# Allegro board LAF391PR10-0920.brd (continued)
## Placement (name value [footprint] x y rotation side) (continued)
JLED1  CVILU_CF5006FD0R0-05-NH  [CVILU_CF5006FD0R0-05-NH_6P]  271.3 9.4 0 top
JLOM1  SANTA_130456-821  [SANTA_130456-821_13P-T]  286.87 80.53 270 bottom
JNGFF1  CONCR_213AAAA42FA  [CONCR_213AAAA42FA_75P]  210.18 38.5 270 bottom
JNGFF2  CONCR_213BAAA42FA  [CONCR_213BAAA42FA_75P]  258.75 28.93 0 bottom
JNGFF3  LCN_DAN05-67356-0103  [LCN_DAN05-67356-0103_75P]  281.1 10.02 180 bottom
JRTC1  ACES_50271-0020N-001  [ACES_50271-0020N-001_2P]  48.15 75.49 90 bottom
JSATA1  ACES_59003-02006-002  [ACES_59003-02006-002_20P]  245.9 7.33 0 bottom
JSD1  T-SOL_158-1000902614  [T-SOL_158-1000902614_23P-T]  85.18 97.85 180 top
JSIM1  T-SOL_5-991503004000-6  [T-SOL_5-991503004000-6_8P-T]  112.1 97.08 0 bottom
JSPI1  ACES_50506-02041-P01  [ACES_50506-02041-P01_20P]  167.6 67.9 325 bottom
JSPK1  ACES_50271-0060N-001  [ACES_50271-0060N-001_6P-T]  257.05 22 270 bottom
JTAG1  @SHORT PADS~D  [SHORTPADS]  274.47 52.78 0 top
JUSB1  ACON_TCRA2-9U1U93  [ACON_TCRA2-9U1U93_9P-T]  285.2 19.95 270 bottom
JUSB2  ACON_TCRA2-9U1U93  [ACON_TCRA2-9U1U93_9P-T]  15.9 29.2 90 bottom
JUSBC1  JAE_DX07BD24JJ2  [JAE_DX07BD24JJ2_24P-T]  7.6 68.86 90 bottom
JUSH1  CVILU_CF5026FD0RK-05-NH  [CVILU_CF5026FD0RK-05-NH_26P-T]  251.1 9.93 0 top
JXDP1  SAMTE_BSH-030-01-L-D-A  [SAMTE_BSH-030-01-L-D-A_60P]  103.14 98.04 180 bottom
LA5  BLM15PX600SN1D_2P  [MURAT_BLM15PX600SN1D_2P]  268.96 24.94 0 top
LA6  BLM15PX330SN1D_2P  [MURAT_BLM15PX330SN1D_2P]  265.75 26.97 0 top
LA7  BLM15PX330SN1D_2P  [MURAT_BLM15PX330SN1D_2P]  263.85 26.97 0 top
LA8  BLM15PX330SN1D_2P  [MURAT_BLM15PX330SN1D_2P]  260.99 26.97 180 top
LA9  BLM15PX330SN1D_2P  [MURAT_BLM15PX330SN1D_2P]  262.95 26.97 180 top
LA10  BLM15PX330SN1D_2P  [MURAT_BLM15PX330SN1D_2P]  273.64 16.91 270 top
LA11  BLM15PX330SN1D_2P  [MURAT_BLM15PX330SN1D_2P]  273.59 18.34 90 top
LA12  BLM15PX600SN1D_2P  [MURAT_BLM15PX600SN1D_2P]  261.38 14.4 0 top
LA13  HCB2012KF-121T50_2P  [TAI-T_HCB2012KF-121T50_2P]  256.95 28.41 90 top
LA14  BLM15PX600SN1D_2P  [MURAT_BLM15PX600SN1D_2P]  254.18 25.15 270 top
LA15  BLM15PX330SN1D_2P  [MURAT_BLM15PX330SN1D_2P]  278.72 7.88 90 top
LA16  BLM15PX330SN1D_2P  [MURAT_BLM15PX330SN1D_2P]  278.72 5.86 270 top
LC1  BLM15GA750SN1D_2P  [MURAT_BLM15GA750SN1D_2P]  127.95 60.12 0 top
LC2  BLM15GA750SN1D_2P  [MURAT_BLM15GA750SN1D_2P]  153.9 68.36 180 bottom
LED3  LTW-C193DC-C_WHITE  [LED_LTW-C193DC-C_2P]  294.5 94.9 0 top
LGA1  -  [LNG2DMTR_LGA12_2X2]  244.76 11.55 270 bottom
LI3  EXC24CQ900U_4P  [PANAS_EXC24CQ900U_4P]  25.83 20.93 270 top
LI7  EXC24CQ900U_4P  [PANAS_EXC24CQ900U_4P]  276.83 26.33 0 top
LI8  MCM1012B900F06BP_4P  [INPAQ_MCM1012B900F06BP_4P]  252.5 28.76 0 top
LI9  MCM1012B900F06BP_4P  [INPAQ_MCM1012B900F06BP_4P]  205.68 37.64 0 bottom
LI16  HCM1012GH900BP_4P  [INPAQ_HCM1012GH900BP_4P]  253.45 31.51 0 bottom
LI17  HCM1012GH900BP_4P  [INPAQ_HCM1012GH900BP_4P]  253.45 33.32 0 bottom
LL1  4.7UH_BRC2012T4R7MD_20%  [TAIYO_BRC2012T4R7MD_2P]  263.1 68.65 0 top
LL2  BLM15PX181SN1D_2P  [MURAT_BLM15PX181SN1D_2P]  257.75 67.05 270 top
LT11  BLM15PX600SN1D_2P  [MURAT_BLM15PX600SN1D_2P]  23.47 81.35 270 top
LV1  BLM15PX221SN1D_2P  [MURAT_BLM15PX221SN1D_2P]  67.99 95.42 0 top
LV3  HCM1012GH900BP_4P  [TAIYO_MCF12102G900-T_4P-NPM]  18.33 43.57 180 bottom
LV6  HCM1012GH900BP_4P  [TAIYO_MCF12102G900-T_4P-NPM]  18.33 47.19 180 bottom
LV9  HCM1012GH900BP_4P  [TAIYO_MCF12102G900-T_4P-NPM]  18.33 45.41 180 bottom
LV12  HCM1012GH900BP_4P  [TAIYO_MCF12102G900-T_4P-NPM]  18.33 48.96 180 bottom
LV14  BLM15PX600SN1D_2P  [MURAT_BLM15PX600SN1D_2P]  280.09 43.74 90 top
LV16  BLM15BB470SN1D_2P  [MURAT_BLM15BB470SN1D_2P]  284.03 61.51 270 top
LV17  BLM15BB470SN1D_2P  [MURAT_BLM15BB470SN1D_2P]  284.03 59.48 270 top
LV18  BLM15BB470SN1D_2P  [MURAT_BLM15BB470SN1D_2P]  284.03 56.54 90 top
LV27  EXC24CQ900U_4P  [PANAS_EXC24CQ900U_4P]  71.64 107.03 90 top
LV30  BLM15PX600SN1D_2P  [MURAT_BLM15PX600SN1D_2P]  284.03 53.64 270 top
LZ1  EXC24CQ900U_4P  [PANAS_EXC24CQ900U_4P]  72.19 101.01 270 top
NOREF  -  []  184.95 77.1 0 top
NOREF#2  -  []  91.15 74.3 0 top
NOREF#3  -  []  124.55 20.7 0 top
NOREF#4  -  []  65.55 78.35 0 top
NOREF#5  -  []  247.75 59.6 0 top
NOREF#6  -  []  149.55 49.8 0 top
NOREF#7  -  []  21.05 15.3 0 top
NOREF#8  -  []  268 74.45 0 top
NOREF#9  -  []  8.85 36.75 0 top
NOREF#10  -  []  25.35 10.82 0 top
NOREF#11  -  []  7.55 12.7 0 top
NOREF#12  -  []  288.05 36.75 0 top
NOREF#13  -  []  91.15 49.8 0 top
NOREF#14  -  []  298.51 26.78 0 top
NOREF#15  -  []  124.55 13.2 0 top
NOREF#16  -  []  6.15 62.43 0 top
NOREF#17  -  []  15.55 38.05 0 top
NOREF#18  -  []  68.06 33.65 0 top
NOREF#19  -  []  151.05 105.15 0 top
NOREF#20  -  []  38.55 100.6 0 top
NOREF#21  -  []  117.34 -26.12 0 top
NOREF#22  -  []  85.37 39.58 0 top
NOREF#23  -  []  243.7 29.25 0 top
NOREF#24  -  []  98.99 -5.54 0 top
NOREF#25  -  []  149.55 74.3 0 top
NOREF#26  -  []  102.02 31.33 90 top
NOREF#27  -  []  6.15 80.53 0 top
NOREF#28  -  []  108.67 25.88 0 top
NOREF#29  -  []  283.55 93.6 0 top
NOREF#30  -  []  280.05 15.3 0 top
NOREF#31  -  []  22.25 161.39 0 top
NOREF#32  -  []  142.57 28.51 180 bottom
NOREF#33  -  []  68.15 26.49 180 bottom
NOREF#34  -  []  161.08 0.92 180 bottom
NOREF#35  -  []  110.93 37.72 180 bottom
PBATT1  DEREN_40-42251-01001RHF  [DEREN_40-42251-01001RHF_10P-T]  41.3 24.06 180 bottom
PC1  2200P_0402_50V7K  [C_0402]  45.84 23.81 270 top
PC2  2200P_0402_50V7K  [C_0402]  45.51 80.75 270 top
PC3  1U_0603_25V6K  [C_0603]  47.96 83.07 0 top
PC4  0.022U_0603_50V7K  [C_0603]  52.92 84.78 90 bottom
PC5  1000P_0603_50V7K  [C_0603]  49.61 94.9 0 top
PC6  0.022U_0603_50V7K  [C_0603]  49.48 92.65 0 bottom
PC7  0.1U_0603_25V7K  [C_0603]  52.72 94.77 90 top
PC8  10U_0805_25V6K  [C_0805]  56.96 91.89 90 top
PC9  0.1U_0402_10V7K  [C_0402]  53.48 90.6 90 bottom
PC10  2.2U_0402_10V6M  [C_0402]  57.18 78 270 bottom
PC11  1000P_0603_50V7K  [C_0603]  53.54 79.18 180 bottom
PC100  100P_0402_50V8J  [C_0402]  147.63 110.49 270 top
PC102  0.1U_0603_25V7K  [C_0603]  140.39 110.97 270 bottom
PC103  100P_0402_50V8J  [C_0402]  147.63 110.49 270 bottom
PC104  10U_0805_25V6K  [C_0805]  146.23 110.5 270 bottom
PC105  10U_0805_25V6K  [C_0805]  146.23 110.5 270 top
PC106  22UF_0805_6.3V6M  [C_0805]  130.07 105.08 180 top
PC107  22UF_0805_6.3V6M  [C_0805]  130.07 108.63 180 top
PC108  22UF_0805_6.3V6M  [C_0805]  130.07 106.85 180 top
PC109  22UF_0805_6.3V6M  [C_0805]  130.07 105.08 180 bottom
PC110  22UF_0805_6.3V6M  [C_0805]  130.07 106.85 180 bottom
PC111  4.7U_0603_6.3V6K  [C_0603]  140.26 102.85 270 bottom
PC112  680P_0603_50V7K  [C_0603]  139.56 105.96 0 top
PC113  1000P_0402_50V7K  [C_0402]  142.3 102.87 270 bottom
PC114  0.1U_0603_25V7K  [C_0603]  46.17 46.44 180 bottom
PC115  100P_0402_50V8J  [C_0402]  43.74 39.92 180 top
PC116  100P_0402_50V8J  [C_0402]  43.74 39.92 180 bottom
PC117  10U_0805_25V6K  [C_0805]  44.12 41.32 180 bottom
PC118  10U_0805_25V6K  [C_0805]  44.12 41.32 180 top
PC119  4.7U_0603_6.3V6K  [C_0603]  40.32 47.65 180 bottom
PC120  22UF_0805_6.3V6M  [C_0805]  38.94 53.22 180 bottom
PC121  22UF_0805_6.3V6M  [C_0805]  38.94 51.51 180 top
PC122  22UF_0805_6.3V6M  [C_0805]  38.92 49.79 180 top
PC123  22UF_0805_6.3V6M  [C_0805]  38.94 51.51 180 bottom
PC124  22UF_0805_6.3V6M  [C_0805]  38.94 53.22 180 top
PC125  680P_0603_50V7K  [C_0603]  42.85 49.71 270 top
PC126  4.7U_0603_6.3V6K  [C_0603]  40.1 45.74 90 top
PC127  1000P_0402_50V7K  [C_0402]  38.79 44.62 270 bottom
PC128  4.7U_0603_6.3V6K~D  [C_0603]  39.41 42.57 180 top
PC129  22UF_0805_6.3V6M  [C_0805]  130.07 108.63 180 bottom
PC130  22UF_0805_6.3V6M  [C_0805]  38.92 49.79 180 bottom
PC131  100P_0402_50V8J  [C_0402]  43.86 44.65 180 top
PC132  100P_0402_50V8J  [C_0402]  38.53 54.52 180 bottom
PC133  1000P_0402_50V7K  [C_0402]  164.43 108.6 180 top
PC134  1000P_0402_50V7K  [C_0402]  162.87 110.37 270 top
PC135  1U_0402_25V6K  [C_0402]  162.01 110.35 270 top
PC136  1U_0402_25V6K  [C_0402]  161.14 110.34 270 top
PC137  1000P_0402_50V7K  [C_0402]  49.38 43.71 90 top
PC138  1000P_0402_50V7K  [C_0402]  48.51 43.69 90 top
PC139  1U_0402_25V6K  [C_0402]  49.77 40.34 270 top
PC140  1U_0402_25V6K  [C_0402]  48.89 40.33 270 top
PC151  100P_0402_50V8J  [C_0402]  166.81 108.84 270 top
PC152  100P_0402_50V8J  [C_0402]  47.55 44.04 90 top
PC153  100P_0402_50V8J  [C_0402]  129.42 110.03 180 bottom
PC200  10U_0603_25V6M  [C_0603]  59.43 60.37 270 bottom
PC201  10U_0603_25V6M  [C_0603]  59.43 60.37 270 top
PC202  0.1U_0402_25V6  [C_0402]  59.64 61.51 90 top
PC203  2200P_0402_50V7K  [C_0402]  58.73 61.51 90 top
PC204  680P_0603_50V7K  [C_0603]  48.95 61.77 270 bottom
PC205  0.1U_0603_16V7K  [C_0603]  52.35 61.51 270 bottom
PC206  1U_0402_6.3V6K  [C_0402]  55.56 62.89 90 top
PC207  2.2U_0402_6.3V6M  [C_0402]  56.44 62.9 90 top
PC208  330P_0402_50V7K  [C_0402]  55.66 63.88 270 bottom
PC209  22U_0603_6.3V6M  [C_0603]  54.79 55.93 270 bottom
PC210  22U_0603_6.3V6M  [C_0603]  54.77 52.18 90 top
PC211  22U_0603_6.3V6M  [C_0603]  53.62 49.77 270 top
PC212  22U_0603_6.3V6M  [C_0603]  55.96 52.18 90 top
PC213  22U_0603_6.3V6M  [C_0603]  54.77 52.18 90 bottom
PC214  10U_0603_6.3V6M  [C_0603]  55.96 52.18 90 bottom
PC216  2200P_0402_50V7K  [C_0402]  57.13 52.12 0 top
PC217  100P_0402_50V8J  [C_0402]  57.1 50.06 0 top
PC218  1U_0402_10V6K  [C_0402]  58.22 56.31 270 bottom
PC219  22U_0603_6.3V6M  [C_0603]  55.88 55.9 0 bottom
PC221  0.1U_0402_10V7K  [C_0402]  59.21 57.6 0 top
PC222  0.1U_0402_10V7K  [C_0402]  58.6 55.33 180 top
PC223  10U_0603_6.3V6M  [C_0603]  53.62 49.77 270 bottom
PC231  100P_0402_50V8J  [C_0402]  57.84 61.51 90 top
PC301  100P_0402_50V8J  [C_0402]  159.38 109.43 0 bottom
PC302  680P_0603_50V7K  [C_0603]  158.68 103.11 0 top
PC303  100P_0402_50V8J  [C_0402]  159.38 109.43 0 top
PC304  0.1U_0603_25V7K  [C_0603]  157.8 103.31 180 bottom
PC305  10U_0603_25V6M  [C_0603]  159.44 108.37 0 bottom
PC306  10U_0603_25V6M  [C_0603]  159.44 108.37 0 top
PC307  330P_0402_50V7K  [C_0402]  165.96 104.97 90 bottom
PC308  22U_0603_6.3V6M  [C_0603]  164.94 100.45 0 bottom
PC309  22U_0603_6.3V6M  [C_0603]  164.94 99.18 0 bottom
PC310  22U_0603_6.3V6M  [C_0603]  164.94 100.45 0 top
PC311  22U_0603_6.3V6M  [C_0603]  164.94 99.18 0 top
PC312  4.7U_0603_6.3V6K  [C_0603]  163.91 103.74 0 bottom
PC313  4.7U_0603_6.3V6K  [C_0603]  163.91 102.54 0 bottom
PC401  470P_0402_50V7K  [C_0402]  169.96 48.71 180 bottom
PC402  0.1U_0402_25V6  [C_0402]  177.35 48.74 90 top
PC403  10U_0603_10V6M  [C_0603]  179.32 49.77 270 bottom
PC404  10U_0603_10V6M  [C_0603]  179.32 49.77 270 top
PC406  22U_0603_6.3V6M  [C_0603]  170.44 53.92 0 bottom
PC407  22U_0603_6.3V6M  [C_0603]  170.44 52.71 0 bottom
PC408  0.1U_0402_25V6  [C_0402]  180.52 49.15 270 top
PC409  100P_0402_50V8J  [C_0402]  178.24 49.27 270 bottom
PC410  470P_0402_50V7K  [C_0402]  175.08 54.69 0 top
PC411  0.1U_0402_25V6  [C_0402]  172.85 97.35 90 top
PC412  10U_0603_10V6M  [C_0603]  175.97 99.24 270 bottom
PC413  10U_0603_10V6M  [C_0603]  175.97 99.24 270 top
PC415  22U_0603_6.3V6M  [C_0603]  169.28 95.68 0 top
PC417  0.1U_0402_25V6  [C_0402]  177.01 98.71 270 top
PC418  100P_0402_50V8J  [C_0402]  177.01 98.7 270 bottom
PC419  470P_0402_50V7K  [C_0402]  169.64 99.77 90 top
PC420  470P_0402_50V7K  [C_0402]  171.96 102.62 180 top
PC424  22U_0603_6.3V6M  [C_0603]  169.28 95.68 0 bottom
PC425  10U_0603_6.3V6M  [C_0603]  170.44 53.92 0 top
PC426  10U_0603_6.3V6M  [C_0603]  170.44 52.7 0 top
PC427  10U_0603_6.3V6M  [C_0603]  169.28 94.41 0 top
PC428  10U_0603_6.3V6M  [C_0603]  169.28 94.41 0 bottom
PC501  22U_0603_6.3V6M  [C_0603]  168.63 106.02 90 bottom
PC503  68P_0402_50V8J  [C_0402]  175.66 104.97 0 bottom
PC504  22U_0603_6.3V6M  [C_0603]  168.63 106 90 top
PC505  0.1U_0402_16V7K  [C_0402]  172.43 107.11 270 top
PC506  680P_0402_50V7K  [C_0402]  172.17 108.37 0 top
PC513  .1U_0402_16V7K  [C_0402]  220.59 11.11 270 top
PC514  4.7U_0603_6.3V6K  [C_0603]  221.37 14.35 270 top
PC515  0.01UF_0402_25V7K  [C_0402]  215.23 14.57 270 top
PC516  22U_0603_6.3V6M  [C_0603]  216.34 15.99 0 top
PC530  10U_0603_6.3V6M  [C_0603]  175.11 109.6 0 top
PC531  10U_0603_6.3V6M  [C_0603]  175.11 109.6 0 bottom
PC601  680P_0402_50V7K  [C_0402]  67.73 73.33 0 bottom
PC602  0.1U_0402_25V6  [C_0402]  59.09 65.49 90 top
PC603  1U_0603_10V6K  [C_0603]  63.01 68.28 180 top
PC604  0.22U_0603_25V7K  [C_0603]  63.02 69.48 180 top
PC605  47P_0402_50V8J~D  [C_0402]  60.87 63.75 90 top
PC606  100U_D_20VM_R55M  [C_D]  66.87 59.19 0 bottom
PC607  100U_D_20VM_R55M  [C_D]  62.4 56.49 90 bottom
PC608  10U 25V M X5R 0603 ZRB  [C_0603]  89.78 88.77 0 top
PC611  0.22U_0603_16V7K  [C_0603]  85.46 89.07 0 bottom
PC612  10U 25V M X5R 0603 ZRB  [C_0603]  89.79 88.76 0 bottom
PC613  330P_0402_50V7K  [C_0402]  66.21 65.35 270 bottom
PC614  2200P_0402_50V7K  [C_0402]  71.1 61.98 180 bottom
PC616  33P_0402_50V8J  [C_0402]  67.71 65.37 270 bottom
PC617  1200P_0402_50V7K  [C_0402]  69.13 60.44 270 top
PC618  330P_0402_50V7K  [C_0402]  70.02 59.53 90 top
PC619  0.01UF_0402_25V7K  [C_0402]  69.01 65.38 270 bottom
PC620  0.082U_0402_16V7K  [C_0402]  68.49 61.39 90 top
PC621  680P_0402_50V7K  [C_0402]  68.64 58.59 180 top
PC622  680P_0603_50V7K  [C_0603]  92.19 83.23 180 top
PC624  0.033U_0402_16V7K  [C_0402]  73.75 63.13 270 bottom
PC625  330P_0402_50V7K  [C_0402]  70.53 65.5 0 bottom
PC626  0.047U_0402_25V7K  [C_0402]  72.88 63.14 270 bottom
PC627  2200P_0402_50V7K  [C_0402]  71.54 62.27 180 top
PC628  33P 50V J NPO 0402  [C_0402]  68.71 70.08 270 bottom
PC629  2200P_0402_50V7K  [C_0402]  75.81 65.1 180 top
PC630  2200P_0402_50V7K  [C_0402]  72.16 71.1 0 top
PC631  4700P_0402_25V7K  [C_0402]  69.13 73.34 0 top
PC632  1000P_0402_50V7K  [C_0402]  64.74 71.57 90 top
PC633  4700P 50V K X7R 0402  [C_0402]  66.5 71.56 90 top
PC635  0.022U_0402_16V7K  [C_0402]  88.43 79.27 90 top
PC636  33P_0402_50V8J  [C_0402]  70.53 67.25 0 bottom
PC637  0.033U 25V K X7R 0402  [C_0402]  64.89 70.84 90 bottom
PC638  0.022U_0402_16V7K  [C_0402]  87.56 79.26 90 top
PC639  1500P_0402_50V7K  [C_0402]  74.88 66.84 270 bottom
PC640  2200P_0402_50V7K  [C_0402]  68.27 73.34 180 top
PC641  .1U_0402_16V7K  [C_0402]  75.49 62.22 90 bottom
PC642  0.022U_0402_16V7K  [C_0402]  72.22 69.77 90 bottom
PC643  330P_0402_50V7K  [C_0402]  69.58 70.08 270 bottom
PC644  .1U_0402_16V7K  [C_0402]  65.95 73.36 180 bottom
PC645  .1U_0402_16V7K  [C_0402]  74.87 69.86 0 top
PC646  0.047U_0402_25V7K  [C_0402]  73.09 69.77 90 bottom
PC647  680P_0402_50V7K  [C_0402]  75.4 65.07 180 bottom
PC649  0.01UF_0402_25V7K  [C_0402]  67.83 70.07 270 bottom
PC650  0.082U_0402_16V7K  [C_0402]  67.38 72.49 270 top
PC651  330P_0402_50V7K  [C_0402]  75.77 67.72 180 bottom
PC652  330P_0402_50V7K  [C_0402]  68.18 74.21 0 top
PC653  0.082U_0402_16V7K  [C_0402]  74.03 67.72 180 bottom
PC654  0.01UF_0402_25V7K  [C_0402]  70.54 68.13 0 bottom
PC655  0.22U_0603_16V7K  [C_0603]  79.79 55.91 90 bottom
PC656  10U 25V M X5R 0603 ZRB  [C_0603]  77.26 58.26 90 top
PC657  10U 25V M X5R 0603 ZRB  [C_0603]  76.06 58.26 90 bottom
PC658  10U 25V M X5R 0603 ZRB  [C_0603]  77.26 58.26 90 bottom
PC659  0.1U_0402_25V6K~D  [C_0402]  75.07 81.63 0 top
PC660  2200P_0402_50V7K  [C_0402]  72.27 57.79 270 top
PC661  1U_0402_10V6K  [C_0402]  85.63 60.33 90 bottom
PC662  680P_0603_50V7K  [C_0603]  77.36 62.12 0 top
PC663  0.22U_0603_16V7K  [C_0603]  61.6 52.78 0 bottom
PC664  10U 25V M X5R 0603 ZRB  [C_0603]  65.26 55 0 bottom
PC665  10U 25V M X5R 0603 ZRB  [C_0603]  65.28 56.23 0 top
PC668  1U_0402_10V6K  [C_0402]  66.15 47.53 0 top
PC669  1U_0402_10V6K  [C_0402]  62.83 49.58 90 bottom
PC670  680P_0603_50V7K  [C_0603]  70.39 52.84 180 top
PC671  0.22U_0603_16V7K  [C_0603]  71.62 81.15 90 bottom
PC672  10U 25V M X5R 0603 ZRB  [C_0603]  74.81 82.66 0 top
PC673  10U 25V M X5R 0603 ZRB  [C_0603]  74.81 82.66 0 bottom
PC674  10U 25V M X5R 0603 ZRB  [C_0603]  65.28 56.22 0 bottom
PC675  10U 25V M X5R 0603 ZRB  [C_0603]  65.26 55 0 top
PC676  1U_0402_10V6K  [C_0402]  82.95 57.17 180 bottom
PC677  1U_0402_10V6K  [C_0402]  71.56 77 90 bottom
PC678  680P_0603_50V7K  [C_0603]  79.58 81.31 180 top
PC682  10U 25V M X5R 0603 ZRB  [C_0603]  76.06 58.26 90 top
PC683  10U 25V M X5R 0603 ZRB  [C_0603]  74.82 83.87 0 top
PC684  10U 25V M X5R 0603 ZRB  [C_0603]  74.82 83.87 0 bottom
PC685  1U_0402_10V6K  [C_0402]  87.55 83.68 0 bottom
PC686  0.1U 25V K X5R 0402  [C_0402]  78.3 59.52 90 bottom
PC687  0.1U 25V K X5R 0402  [C_0402]  63.06 53.84 180 bottom
PC688  0.1U 25V K X5R 0402  [C_0402]  75.07 81.63 0 bottom
PC689  1000P_0402_50V7K  [C_0402]  62.29 56.71 180 top
PC690  1000P_0402_50V7K  [C_0402]  62.11 57.6 180 top
PC691  1U_0402_25V6K  [C_0402]  65.59 60.52 90 top
PC692  1U_0402_25V6K  [C_0402]  63.86 60.52 90 top
PC695  100P_0402_50V8J  [C_0402]  74.01 57.79 270 top
PC696  100P_0402_50V8J  [C_0402]  64.72 59.94 90 top
PC697  1U_0402_10V6K  [C_0402]  75.12 74.3 0 bottom
PC902  0.1U_0402_25V6  [C_0402]  26.37 32.37 270 bottom
PC903  100P_0402_50V8J  [C_0402]  26.37 32.37 270 top
PC904  10U_0805_25VAK  [C_0805]  25.05 32.25 270 top
PC905  10U_0805_25VAK  [C_0805]  25.05 32.25 270 bottom
PC906  10U_0805_25VAK  [C_0805]  23.33 32.25 270 bottom
PC909  15U_B2_25VM_R100M  [C_B2]  23.73 34.88 180 top
PC911  10U_0805_25VAK  [C_0805]  23.34 32.25 270 top
PC913  10U_0805_25VAK  [C_0805]  26.08 28.56 270 top
PC914  10U_0805_25VAK  [C_0805]  24.35 28.56 270 bottom
PC915  10U_0805_25VAK  [C_0805]  24.34 28.58 270 top
PC916  10U_0805_25VAK  [C_0805]  26.06 28.56 270 bottom
PC921  15U_B2_25VM_R100M  [C_B2]  22.1 28.33 0 bottom
PC925  4.7U_0402_6.3V6M  [C_0402]  30.07 39.87 270 bottom
PC926  1U 25V K X5R 0402  [C_0402]  29.91 41.38 90 top
PC927  1U 25V K X5R 0402  [C_0402]  30.78 41.38 90 top
PC928  100P_0402_50V6  [C_0402]  33.99 22.91 270 top
PC929  2200P_0402_50V7K  [C_0402]  34.88 22.91 270 top
PC930  0.22U_0603_25V7K  [C_0603]  32.63 39.01 90 bottom
PC931  1U_0603_25V6  [C_0603]  25.39 40.9 0 bottom
PC932  1U_0402_6.3V6K  [C_0402]  32.82 43.57 0 top
PC933  1U_0402_6.3V6K  [C_0402]  26.98 41.95 180 bottom
PC934  0.22U_0603_25V7K  [C_0603]  36.76 42.99 180 bottom
PC935  10U_0805_25VAK  [C_0805]  42.39 26.98 0 bottom
PC936  10U_0805_25VAK  [C_0805]  42.4 26.98 0 top
PC937  4700P_0402_25V7K  [C_0402]  36.5 22.65 90 top
PC938  10P_0402_50V8J  [C_0402]  27.59 46.92 180 top
PC939  0.1U_0402_25V6  [C_0402]  33.74 44.45 180 top
PC940  680P_0603_50V7K  [C_0603]  34.83 35.61 180 top
PC941  680P_0603_50V7K  [C_0603]  34.47 29.33 180 top
PC942  1U 25V K X5R 0402  [C_0402]  33.74 45.32 180 top
PC943  560P_0402_50V7K  [C_0402]  30.85 46.7 270 top
PC944  0.01UF_0402_25V7K  [C_0402]  30.88 49.81 90 top
PC945  1U_0402_25V6M  [C_0402]  35.09 46.44 270 bottom
PC946  0.22U_0402_25V6K  [C_0402]  33.73 46.2 180 top
PC947  0.1U_0402_25V6  [C_0402]  31.73 46.7 270 top
PC949  0.1U_0402_10V7K  [C_0402]  28.14 51.13 0 top
PC950  0.1U_0402_25V6  [C_0402]  35.89 46.43 180 top
PC951  10U_0805_25VAK  [C_0805]  20.62 33.29 270 bottom
PC952  10U_0805_25VAK  [C_0805]  20.62 33.29 270 top
PC955  0.1U_0402_25V6  [C_0402]  28.35 43.48 0 top
PC956  1000P_0402_50V7K  [C_0402]  21.17 26.3 270 top
PC957  1000P_0402_50V7K  [C_0402]  22.04 26.3 270 bottom
PC958  1U_0402_25V6K  [C_0402]  22.04 26.3 270 top
PC959  1U_0402_25V6K  [C_0402]  21.17 26.3 270 bottom
PC1001  22U_0603_6.3V6M  [C_0603]  78.6 66.59 180 bottom
PC1002  22U_0603_6.3V6M  [C_0603]  79.79 73.47 90 top
PC1003  22U_0603_6.3V6M  [C_0603]  78.6 69.13 180 bottom
PC1004  22U_0603_6.3V6M  [C_0603]  79.79 73.47 90 bottom
PC1005  22U_0603_6.3V6M  [C_0603]  119.85 61.97 0 top
PC1006  22U_0603_6.3V6M  [C_0603]  119.06 59.5 180 top
PC1007  22U_0603_6.3V6M  [C_0603]  119.85 60.76 0 top
PC1008  22U_0603_6.3V6M  [C_0603]  118.85 61.97 180 top
PC1009  22U_0603_6.3V6M  [C_0603]  118.86 60.76 180 top
PC1010  22U_0603_6.3V6M  [C_0603]  115.1 60.77 0 top
PC1011  22U_0603_6.3V6M  [C_0603]  115.07 61.98 0 top
PC1012  22U_0603_6.3V6M  [C_0603]  118.86 64.39 180 top
PC1013  22U_0603_6.3V6M  [C_0603]  118.86 63.19 180 top
PC1014  22U_0603_6.3V6M  [C_0603]  80.32 53.93 0 top
PC1015  22U_0603_6.3V6M  [C_0603]  84.08 53.93 180 bottom
PC1016  22U_0603_6.3V6M  [C_0603]  84.08 53.93 180 top
PC1017  22U_0603_6.3V6M  [C_0603]  107.56 61.24 90 top
PC1018  22U_0603_6.3V6M  [C_0603]  105.16 64.99 270 top
PC1019  22U_0603_6.3V6M  [C_0603]  106.36 65 270 top
PC1020  22U_0603_6.3V6M  [C_0603]  107.57 64.99 270 top
PC1021  22U_0603_6.3V6M  [C_0603]  108.78 65 270 top
PC1022  22U_0603_6.3V6M  [C_0603]  85.15 53.96 0 top
PC1023  22U_0603_6.3V6M  [C_0603]  85.14 53.96 0 bottom
PC1024  22U_0603_6.3V6M  [C_0603]  80.28 47.34 180 top
PC1025  22U_0603_6.3V6M  [C_0603]  105.16 61.24 90 top
PC1026  22U_0603_6.3V6M  [C_0603]  106.36 61.24 90 top
PC1030  1U_0201_6.3V6M  [C_0201]  118.24 57.96 0 top
PC1031  1U_0201_6.3V6M  [C_0201]  116.02 67.08 0 top
PC1032  1U_0201_6.3V6M  [C_0201]  117.85 67.07 180 top
PC1033  1U_0201_6.3V6M  [C_0201]  117.86 66.51 180 top
PC1034  1U_0201_6.3V6M  [C_0201]  116.02 66.51 0 top
PC1035  1U_0201_6.3V6M  [C_0201]  123.75 67.08 270 top
PC1036  1U_0201_6.3V6M  [C_0201]  116.05 65.88 0 top
PC1037  1U_0201_6.3V6M  [C_0201]  117.81 65.89 180 top
PC1038  1U_0201_6.3V6M  [C_0201]  120.09 57.97 180 top
PC1039  1U_0201_6.3V6M  [C_0201]  119.02 65.92 180 top
PC1040  1U_0201_6.3V6M  [C_0201]  107.13 67.08 180 top
PC1041  1U_0201_6.3V6M  [C_0201]  108.35 60.45 270 top
PC1042  1U_0201_6.3V6M  [C_0201]  109.5 66.51 180 top
PC1043  1U_0201_6.3V6M  [C_0201]  109.5 67.08 180 top
PC1044  1U_0201_6.3V6M  [C_0201]  107.77 60.44 270 top
PC1045  1U_0201_6.3V6M  [C_0201]  110.26 64.01 270 top
PC1046  1U_0201_6.3V6M  [C_0201]  107.73 66.51 0 top
PC1047  1U_0201_6.3V6M  [C_0201]  107.74 65.95 0 top
PC1048  1U_0201_6.3V6M  [C_0201]  110.26 62.24 90 top
PC1049  1U_0201_6.3V6M  [C_0201]  108.92 60.47 270 top
PC1050  1U_0201_6.3V6M  [C_0201]  122.61 67.08 270 top
PC1051  1U_0201_6.3V6M  [C_0201]  123.18 67.08 270 top
PC1052  1U_0201_6.3V6M  [C_0201]  121.41 65.91 180 top
PC1053  1U_0201_6.3V6M  [C_0201]  121.85 57.94 180 top
PC1055  1U_0201_6.3V6M  [C_0201]  107.73 67.07 0 top
PC1056  1U_0201_6.3V6M  [C_0201]  109.69 62.23 90 top
PC1057  22U_0603_6.3V6M  [C_0603]  100.92 87.84 90 top
PC1058  22U_0603_6.3V6M  [C_0603]  102.18 87.86 90 top
PC1059  22U_0603_6.3V6M  [C_0603]  102.18 87.87 90 bottom
PC1060  22U_0603_6.3V6M  [C_0603]  100.92 87.85 90 bottom
PC1061  22U_0603_6.3V6M  [C_0603]  78.59 74.13 180 top
PC1062  330U_D2_2.5VM_R9M  [C_D2]  82.69 66.65 0 top
PC1063  330U_D2_2.5VM_R9M  [C_D2]  89.98 61.24 90 bottom
PC1064  22U_0603_6.3V6M  [C_0603]  78.6 71.67 180 top
PC1065  22U_0603_6.3V6M  [C_0603]  78.59 74.13 180 bottom
PC1066  22U_0603_6.3V6M  [C_0603]  78.6 67.86 180 top
PC1067  22U_0603_6.3V6M  [C_0603]  78.6 71.67 180 bottom
PC1068  22U_0603_6.3V6M  [C_0603]  78.61 67.87 180 bottom
PC1069  22U_0603_6.3V6M  [C_0603]  78.6 70.4 180 top
PC1070  22U_0603_6.3V6M  [C_0603]  78.6 69.13 180 top
PC1071  22U_0603_6.3V6M  [C_0603]  78.62 72.9 180 top
PC1072  22U_0603_6.3V6M  [C_0603]  78.61 72.9 180 bottom
PC1073  22U_0603_6.3V6M  [C_0603]  115.06 64.4 0 top
PC1074  22U_0603_6.3V6M  [C_0603]  115.32 59.51 0 top
PC1075  22U_0603_6.3V6M  [C_0603]  122.24 63.19 0 top
PC1076  22U_0603_6.3V6M  [C_0603]  115.06 63.19 0 top
PC1077  22U_0603_6.3V6M  [C_0603]  78.6 70.4 180 bottom
PC1078  22U_0603_6.3V6M  [C_0603]  119.85 63.19 0 top
PC1079  22U_0603_6.3V6M  [C_0603]  119.84 64.39 0 top
PC1080  22U_0603_6.3V6M  [C_0603]  120.06 59.5 0 top
PC1081  22U_0603_6.3V6M  [C_0603]  78.6 66.59 180 top
PC1082  22U_0603_6.3V6M  [C_0603]  122.23 61.9 0 top
PC1083  1U_0201_6.3V6M  [C_0201]  119.64 67.07 0 top
PC1084  1U_0201_6.3V6M  [C_0201]  119.04 66.51 180 top
PC1085  1U_0201_6.3V6M  [C_0201]  122.04 67.08 270 top
PC1086  1U_0201_6.3V6M  [C_0201]  114.85 66.52 0 top
PC1087  1U_0201_6.3V6M  [C_0201]  116.05 65.3 0 top
PC1088  1U_0201_6.3V6M  [C_0201]  114.86 65.9 0 top
PC1089  1U_0201_6.3V6M  [C_0201]  114.85 65.3 0 top
PC1090  1U_0201_6.3V6M  [C_0201]  114.85 67.08 0 top
PC1091  1U_0201_6.3V6M  [C_0201]  121.42 65.32 180 top
PC1092  1U_0201_6.3V6M  [C_0201]  119.03 65.33 180 top
PC1093  1U_0201_6.3V6M  [C_0201]  117.81 65.32 180 top
PC1094  1U_0201_6.3V6M  [C_0201]  119.64 65.34 0 top
PC1095  1U_0201_6.3V6M  [C_0201]  119.65 65.92 0 top
PC1096  1U_0201_6.3V6M  [C_0201]  121.41 66.49 180 top
PC1097  1U_0201_6.3V6M  [C_0201]  119.65 66.5 0 top
PC1098  1U_0201_6.3V6M  [C_0201]  119.03 67.08 180 top
PC1099  1U_0201_6.3V6M  [C_0201]  121.41 67.07 180 top
PC1127  330U_D2_2.5VM_R9M  [C_D2]  85.23 61.96 0 top
PC1128  330U_D2_2.5VM_R9M  [C_D2]  87.82 57.13 180 top
PC1129  22U_0603_6.3V6M  [C_0603]  105.55 66.13 0 top
PC1132  22U_0603_6.3V6M  [C_0603]  80.32 53.93 0 bottom
PC1133  22U_0603_6.3V6M  [C_0603]  108.79 61.24 90 top
PC1134  22U_0603_6.3V6M  [C_0603]  90.61 57.51 270 top
PC1136  22U_0603_6.3V6M  [C_0603]  80.28 47.34 180 bottom
PC1137  22U_0603_6.3V6M  [C_0603]  90.61 57.51 270 bottom
PC1139  22U_0603_6.3V6M  [C_0603]  127.13 66.34 270 top
PC1140  22U_0603_6.3V6M  [C_0603]  124.61 63.19 0 top
PC1141  22U_0603_6.3V6M  [C_0603]  124.62 64.39 0 top
PC1142  22U_0603_6.3V6M  [C_0603]  124.62 65.59 0 top
PC1143  22U_0603_6.3V6M  [C_0603]  99.71 89.02 90 top
PC1144  22U_0603_6.3V6M  [C_0603]  99.7 89.01 90 bottom
PC1145  22U_0603_6.3V6M  [C_0603]  123.61 65.61 180 top
PC1146  22U_0603_6.3V6M  [C_0603]  123.64 64.4 180 top
PC1147  1U_0201_6.3V6M  [C_0201]  124.42 66.51 0 top
PC1148  1U_0201_6.3V6M  [C_0201]  126.61 58.29 270 top
PC1149  1U_0201_6.3V6M  [C_0201]  126.04 58.29 270 top
PC1150  1U_0201_6.3V6M  [C_0201]  124.41 67.08 0 top
PC1151  1U_0201_6.3V6M  [C_0201]  126.18 67.08 180 top
PC1152  1U_0201_6.3V6M  [C_0201]  126.18 66.51 180 top
PC1153  1U_0201_6.3V6M  [C_0201]  126.83 67.1 0 top
PC1175  22U_0603_6.3V6M  [C_0603]  77.98 56.08 180 top
PC1176  22U_0603_6.3V6M  [C_0603]  77.98 56.08 180 bottom
PC1177  22U_0603_6.3V6M  [C_0603]  105.61 60.13 0 top
PC1178  22U_0603_6.3V6M  [C_0603]  85.14 52.75 0 top
PC1179  22U_0603_6.3V6M  [C_0603]  90.42 58.59 0 bottom
PC1180  22U_0603_6.3V6M  [C_0603]  90.42 58.59 0 top
PC1181  22U_0603_6.3V6M  [C_0603]  85.15 52.75 0 bottom
PC1191  100P_0402_50V8J  [C_0402]  86.72 69.71 0 top
PC1192  100P_0402_50V8J  [C_0402]  87.08 66.44 270 bottom
PC1193  100P_0402_50V8J  [C_0402]  162.67 110.49 270 bottom
PC1194  100P_0402_50V8J  [C_0402]  173.08 110.82 270 bottom
PC1195  100P_0402_50V8J  [C_0402]  165.66 73.33 270 bottom
PC1196  100P_0402_50V8J  [C_0402]  178.82 97.3 180 bottom
PC1198  100P_0402_50V8J  [C_0402]  98.67 89.12 90 top
PC1199  100P_0402_50V8J  [C_0402]  97.78 89.12 90 top
PC1201  0.01UF 25V +-10% X7R 0402  [C_0402]  60.67 73.88 180 top
PC1202  0.47U 25V K X7R 0603  [C_0603]  41.85 64.11 90 top
PC1203  1500P_0402_50V7K  [C_0402]  36.84 74.14 270 top
PC1204  0.1U_0402_10V7K  [C_0402]  40.51 73.26 270 top
PC1205  100P_0402_50V8J~D  [C_0402]  60.6 78.85 90 top
PC1206  220P_0402_50V8J~D  [C_0402]  56.26 79.63 180 top
PC1207  1200P_0402_50V7K  [C_0402]  58.85 78.73 90 top
PC1208  1000P_0402_50V7K  [C_0402]  19.07 78.14 0 bottom
PC1209  0.1U_0402_25V6  [C_0402]  19.05 81.72 0 bottom
PC1210  1500P_0402_50V7K  [C_0402]  39.06 64.04 0 top
PC1211  100P_0402_50V8J  [C_0402]  53.53 73.51 180 top
PC1212  100P_0402_50V8J  [C_0402]  55.67 71.21 180 top
PC1213  1200P_0402_50V7K  [C_0402]  57.37 71.22 0 top
PC1214  0.01UF_0402_25V7K  [C_0402]  58.25 69.5 270 top
PC1215  100P_0402_50V8J  [C_0402]  19.07 79.04 0 bottom
PC1216  100P_0402_50V8J  [C_0402]  19.05 80.83 0 bottom
PC1217  1500P_0402_50V7K  [C_0402]  62.76 83.97 0 top
PC1321  330U_D2_2.5VM_R9M  [C_D2]  84.46 78.32 180 top
PC1322  22U_0603_6.3V6M  [C_0603]  112.46 64.84 180 top
PC1323  22U_0603_6.3V6M  [C_0603]  112.44 63.64 180 top
PC1324  22U_0603_6.3V6M  [C_0603]  112.41 62.43 180 top
PC1325  22U_0603_6.3V6M  [C_0603]  111.28 61.21 180 top
PC1326  22U_0603_6.3V6M  [C_0603]  111.27 60 180 top
PC1327  22U_0603_6.3V6M  [C_0603]  113.52 63.83 270 top
PC1328  1U_0201_6.3V6M  [C_0201]  109.68 64 270 top
PC1329  1U_0201_6.3V6M  [C_0201]  109.7 65.14 0 top
PC1330  1U_0201_6.3V6M  [C_0201]  114.71 57.6 0 top
PC1331  1U_0201_6.3V6M  [C_0201]  113.95 57.61 180 top
PC1332  1U_0201_6.3V6M  [C_0201]  112.17 58.19 0 top
PC1333  1U_0201_6.3V6M  [C_0201]  113.95 58.19 180 top
PC1334  1U_0201_6.3V6M  [C_0201]  114.71 58.19 0 top
PD1  -  [TVNST52302AB0_SOT523-3]  34.79 16.5 180 top
PD2  -  [TVNST52302AB0_SOT523-3]  36.79 16.5 180 top
PD3  BAS40CW SOT-323  [DB3J315E0L_SMINI3-F2-B3]  48.15 81.88 0 top
PD4  AZ5125-02S.R7G_SOT23-3  [PESD5V0U2BT_SOT23-3]  39.28 88.66 270 top
PD5  S SCH DIO 5A 100V 15UA 0.88V TO227-3  [PDS5100H-13_POWERDI5-3]  56.38 86.34 90 top
PD6  -  [DFLS160-7_POWERDI123-2]  57.98 95.38 180 top
PD901  DIO 30MA 30V 0.5UA 0.4V SOD323-2  [SDMK0340L-7-F_SOD323-2]  28.73 37.45 0 top
PD903  -  [RB520SM-30T2R_EMD2-2]  28.74 39.15 0 top
PD904  DIO 30MA 30V 0.5UA 0.4V SOD323-2  [SDMK0340L-7-F_SOD323-2]  25.33 40.94 180 top
PD905  BAT54CW-7-F SOT-323  [BAT54CW_SOT323-3]  25.63 50.54 270 top
PD906  DIO SMF4L22A SOD123FL-2  [SMF22A-SOD123FL-2-S]  25.27 38.31 180 top
PD1202  S SCH DIO 5A 100V 15UA 0.88V TO227-3  [PDS5100H-13_POWERDI5-3]  46.26 68.26 270 top
PD1205  DIO 30MA 30V 0.5UA 0.4V SOD323-2  [SDMK0340L-7-F_SOD323-2]  54.79 73.81 90 top
PD1801  BAT54CW-7-F SOT-323  [BAT54CW_SOT323-3]  60.54 75.02 180 top
PH601  470K_0402_5%_B25/50 4700K  [R_0402]  86.89 64.68 180 bottom
PH602  10K_0402_5%_B25/50 4250K  [R_0402]  85.83 73.57 90 bottom
PH603  470K_0402_5%_B25/50 4700K  [R_0402]  71.29 55.94 180 bottom
PH604  10KB_0402_5%  [R_0402]  95.26 82.47 0 bottom
PH605  10K_0402_5%_B25/50 4250K  [R_0402]  72.14 55.93 0 bottom
PJP1  PAD-OPEN1X1M  [JUMP_43X39]  129.44 81.66 0 bottom
PJP2  PAD-OPEN1X1M  [JUMP_43X39]  129.13 87.05 90 bottom
PJP3  PAD-OPEN1X3M  [JUMP_43X118]  142.21 84.37 270 bottom
PJP4  PAD-OPEN1X1M  [JUMP_43X39]  155.4 52.17 270 top
PJP7  PAD-OPEN1X1M  [JUMP_43X39]  12.76 67 90 top
PJP8  PAD-OPEN 1X3M  [JUMP_43X118]  34.04 53.49 270 bottom
PJP12  PAD-OPEN1X1M  [JUMP_43X39]  69.19 86.28 0 top
PJP13  PAD-OPEN1X2M  [JUMP_43X79]  72.66 98.65 180 top
PJP14  PAD-OPEN1X2M  [JUMP_43X79]  83.54 90.47 180 top
PJP15  PAD-OPEN1X1M  [JUMP_43X39]  251.21 33.7 180 top
PJP16  PAD-OPEN1X1M  [JUMP_43X39]  243.08 34.38 180 top
PJP17  PAD-OPEN1X2M  [JUMP_43X79]  250.2 36.75 0 top
PJP18  PAD-OPEN1X1M  [JUMP_43X39]  242.74 37.13 270 top
PJP19  PAD-OPEN1X1M  [JUMP_43X39]  276.71 21 0 bottom
PJP20  PAD-OPEN1X1M  [JUMP_43X39]  240.57 44.04 90 top
PJP21  PAD-OPEN1X1M  [JUMP_43X39]  240.57 47.37 270 top
PJP22  PAD-OPEN1X1M  [JUMP_43X39]  266.63 62.48 270 top
PJP31  PAD-OPEN1X3M  [JUMP_43X118]  248.09 14.69 270 bottom
PJP32  PAD-OPEN1X1M  [JUMP_43X39]  243.77 11.27 270 top
PJP33  PAD-OPEN1X1M  [JUMP_43X39]  244.25 7.36 270 top
PJP34  PAD-OPEN1X2M  [JUMP_43X79]  246.94 13.8 270 top
PJP35  PAD-OPEN1X1M  [JUMP_43X39]  199.85 27.02 270 top
PJP36  PAD-OPEN1X2M  [JUMP_43X79]  211.43 37.72 90 top
PJP37  PAD-OPEN1X1M  [JUMP_43X39]  234.5 43.66 90 top
PJP38  PAD-OPEN1X1M  [JUMP_43X39]  174.62 58.38 270 top
PJP39  PAD-OPEN1X3M  [JUMP_43X118]  173.54 67.1 90 top
PJP40  PAD-OPEN1X2M  [JUMP_43X79]  213.8 29.13 270 top
PJP41  PAD-OPEN1X3M  [JUMP_43X118]  229.08 40.43 180 top
PJP42  PAD-OPEN1X1M  [JUMP_43X39]  238.51 35.35 270 top
PJP100  PAD-OPEN 1X2M~D  [JUMP_43X79]  157.27 109.91 180 top
PJP101  PAD-OPEN 1X2M~D  [JUMP_43X79]  46.96 41.69 180 top
PJP102  -  [JUMP_43X118]  129.21 102.45 270 bottom
PJP103  -  [JUMP_43X118]  39 56.73 180 top
PJP200  -  [JUMP_43X118]  56.84 50.32 270 bottom
PJP201  -  [JUMP_43X39]  58.2 54.28 270 bottom
PJP202  PAD-OPEN 1X2M~D  [JUMP_43X79]  62.31 59.97 180 top
PJP301  PAD-OPEN 1X2M~D  [JUMP_43X79]  157.01 110.15 270 bottom
PJP302  -  [JUMP_43X118]  162.28 99.61 180 top
PJP391  PAD-OPEN1X1M  [JUMP_43X39]  164.13 53.34 90 top
PJP401  -  [JUMP_43X79]  170.93 55.64 90 bottom
PJP402  -  [JUMP_43X79]  167.64 94.5 180 bottom
PJP403  PAD-OPEN1X1M  [JUMP_43X39]  179.13 51.88 270 bottom
PJP404  PAD-OPEN1X1M  [JUMP_43X39]  176.2 101.46 270 bottom
PJP501  PAD-OPEN1X1M  [JUMP_43X39]  178.13 107.27 90 bottom
PJP502  PAD-OPEN1X1M  [JUMP_43X39]  168.57 104.42 180 bottom
PJP505  PAD-OPEN1X1M  [JUMP_43X39]  220.72 16.68 270 top
PJP506  PAD-OPEN1X1M  [JUMP_43X39]  214.62 15.73 90 top
PJP601  PAD-OPEN 4X4M  [JUMP_43X118]  61.59 52 270 top
PJP603  PAD-OPEN1X1M  [JUMP_43X39]  88.57 88.17 180 top
PJP901  PAD-OPEN 4X4M  [JUMP_43X118-NPM]  24.41 37.05 270 bottom
PJP1202  -  [JUMP_43X118]  45.07 60.95 90 top
PJPDC1  ACES_50290-0050N-001  [ACES_50290-0050N-001_5P-T]  44.52 86.8 90 bottom
PL1  FBMJ4516HS720NT_2P  [TAIYO_FBMJ4516HS720NT_2P]  42.01 23.21 270 top
PL2  FBMJ4516HS720NT_2P  [TAIYO_FBMJ4516HS720NT_2P]  44.26 23.21 270 top
PL3  BLM15AG102SN1D_2P  [MURAT_BLM15AG102SN1D_2P]  43.09 87.24 90 top
PL4  FBMJ4516HS720NT_2P  [TAIYO_FBMJ4516HS720NT_2P]  50.11 93.16 0 top
PL100  1.5UH_9A_20%_7X7X3_M  [L_7X7X3_M_2P]  138.59 106.22 180 bottom
PL101  1.5UH_9A_20%_7X7X3_M  [L_7X7X3_M_2P]  43.27 48.98 90 bottom
PL201  S COIL 1UH +-20% PCMB063T-1R0MS 12A  [CYNTE_PCMB063T-1R0MS_2P]  50.53 56.9 270 bottom
PL301  0.68UH_7.9A_20%_5X5X3_M  [L_5X5X3_M_2P]  158.32 99.79 0 bottom
PL402  1UH_1277AS-H-1R0N-P2_3.3A_30%  [MAG_MLV-FY12N1R0M-O1L_2P]  172.08 50.65 180 bottom
PL404  1UH_1277AS-H-1R0N-P2_3.3A_30%  [MAG_MLV-FY12N1R0M-O1L_2P]  168.79 99.7 270 bottom
PL405  3A_Z120_40M_0603_2P  [3A_Z120_0603_2P]  180.91 51.88 270 bottom
PL406  3A_Z120_40M_0603_2P  [3A_Z120_0603_2P]  177.98 101.43 270 bottom
PL501  1UH_1277AS-H-1R0N-P2_3.3A_30%  [MAG_MLV-FY12N1R0M-O1L_2P]  170.79 108.16 270 bottom
PL502  3A_Z120_40M_0603_2P  [3A_Z120_0603_2P]  178.11 106.99 90 top
PL602  9A Z80 10M 1812_2P  [9A_Z80_1812_2P-NPM]  61.52 53.25 270 top
PL610  0.15UH_MMD-06CZER15MEX5L__35A_20%  [L_7X7X3_M]  82.88 72.16 270 bottom
PL612  0.15UH_MMD-06CZER15MEX5L__35A_20%  [L_7X7X3_M]  77.92 51.7 180 bottom
PL613  0.15UH_MMD-06CZER15MEX5L__35A_20%  [L_7X7X3_M]  82.92 76.06 90 bottom
PL614  0.47UH_MMD05CZR47M_12A_20%  [MAG_MMD05CZR47M_4P]  98.52 85.75 180 bottom
PL901  1UH +-20% 6.6A 5X5X3 MOLDING  [MAGLA_MMD-05CZ-1R0M-M7L_2P]  24.41 34.48 90 bottom
PL902  2.2UH_PCMB103T-2R2MS_13A_20%  [CYNTE_PCMB103T-2R2MS_2P]  39.11 37.95 270 bottom
PL1201  5A_Z80_20M_0805_2P  [TAI-T_HCB2012KF-121T50_2P]  15.93 79.03 90 bottom
PL1202  5A_Z80_20M_0805_2P  [TAI-T_HCB2012KF-121T50_2P]  17.73 79.03 90 bottom
PQ1  -  [DMN65D8LDW-7_SOT363-6]  64.74 81.61 90 top
PQ2  -  [FDV301N-G_SOT23-3]  44.79 85.72 270 top
PQ3  MMST3904-7-F_SOT323~D  [MMST3904-7-F_SOT323-3]  45.98 82.55 90 top
PQ4  EMZB08P03V 1P EDFN3X3-8  [FDMC6679AZ_MLP8-5]  52.78 84.55 90 top
PQ5  AO3409 P-CHANNEL SOT-23  [NTR4502PT1G_SOT23-3]  61.77 86.42 270 top
PQ6  L2N7002WT1G_SC70-3  [DMN65D8LW-7_SOT323-3]  52.65 94.48 180 bottom
PQ7  L2N7002WT1G_SC70-3  [DMN65D8LW-7_SOT323-3]  60.17 84.77 0 top
PQ8  L2N7002WT1G_SC70-3  [DMN65D8LW-7_SOT323-3]  50.04 82.21 270 bottom
PQ9  EMZB08P03V 1P EDFN3X3-8  [FDMC6679AZ_MLP8-5]  52.03 91.13 180 top
PQ614  PE642DT 2N PDFN3X3S  [AON7934_DFN3X3A8-10]  89.63 86.9 0 bottom
PQ904  FDPC5030SG 2N POWER CLIP 56-8  [AOE6930_DFN5X6E8-10]  27.72 27.02 90 bottom
PQ905  FDPC5030SG 2N POWER CLIP 56-8  [AOE6930_DFN5X6E8-10]  27.73 32.53 90 bottom
PQ906  EMZB08P03V 1P EDFN3X3-8  [FDMC6679AZ_MLP8-5]  39.84 23.52 180 top
PQ909  L2N7002WT1G 1N SC-70-3  [DMN65D8LW-7_SOT323-3]  25.37 47.62 270 top
PQ1201  -  [DMN65D8LDW-7_SOT363-6]  39.09 71.16 180 top
PQ1202  EMZB08P03V 1P EDFN3X3-8  [FDMC6679AZ_MLP8-5]  51.42 66.73 180 top
PQ1203  AO3409 P-CHANNEL SOT-23  [NTR4502PT1G_SOT23-3]  52.36 68.59 0 top
PQ1204  -  [DMN65D8LDW-7_SOT363-6]  35.13 69.26 0 top
PQ1205  L2N7002WT1G_SC70-3  [DMN65D8LW-7_SOT323-3]  34.91 75.95 90 top
PQ1206  EMZB08P03V 1P EDFN3X3-8  [FDMC6679AZ_MLP8-5]  41.48 63 180 top
PQ1207  S TR DMN65D8LDW-7 2N SOT363-6  [DMN66D0LDW-7_SOT363-6]  44.45 53.08 90 top
PQ1208  S TR DMN65D8LDW-7 2N SOT363-6  [DMN66D0LDW-7_SOT363-6]  47.25 50.99 0 top
PQ1209  -  [DMN65D8LDW-7_SOT363-6]  61.61 71.01 90 top
PQ1210  S TR DMN65D8LDW-7 2N SOT363-6  [DMN66D0LDW-7_SOT363-6]  43.65 57.31 90 top
PQ1211  S TR DMN65D8LDW-7 2N SOT363-6  [DMN66D0LDW-7_SOT363-6]  44.78 56.44 0 top
PQ1212  L2N7002WT1G_SC70-3  [DMN65D8LW-7_SOT323-3]  50.93 75.37 0 top
PQ1213  EMZB08P03V 1P EDFN3X3-8  [FDMC6679AZ_MLP8-5]  48.24 62.38 270 top
PQ1214  -  [DMN65D8LDW-7_SOT363-6]  42.91 76.21 180 top
PQ1215  AO3409 P-CHANNEL SOT-23  [NTR4502PT1G_SOT23-3]  41.93 68.16 0 top
PQ1216  L2N7002WT1G_SC70-3  [DMN65D8LW-7_SOT323-3]  33.69 48.21 270 bottom
PR1  100K_0402_5%  [R_0402]  33.36 17.04 90 top
PR2  1K_0402_5%  [R_0402]  46.39 79.83 90 top
PR3  0_0402_5%  [R_0402]  43.99 87.23 90 top
PR4  2.2K_0402_5%  [R_0402]  48.55 85.49 270 top
PR5  33_0402_5%  [R_0402]  48.55 87.23 270 top
PR6  100K_0402_1%  [R_0402]  43.08 85.47 90 top
PR7  10K_0402_1%  [R_0402]  47.06 82.25 90 top
PR8  15K_0402_1%  [R_0402]  42.95 81.18 90 top
PR10  300K_0402_5%  [R_0402]  65.58 87.53 270 top
PR11  499K_0402_1%  [R_0402]  53.47 88.75 270 top
PR12  1M_0402_5%  [R_0402]  50.35 93.7 180 bottom
PR13  4.7K_0805_5%  [R_0805]  53.89 95.14 0 top
PR14  100K_0402_5%  [R_0402]  58.27 91.73 90 top
PR15  100K_0402_5%  [R_0402]  65.58 85.64 270 top
PR16  49.9K_0402_1%  [R_0402]  60.03 86.82 270 top
PR17  100K_0402_5%  [R_0402]  67.48 83.1 180 top
PR18  1M_0402_5%  [R_0402]  49.43 94.58 0 bottom
PR19  0_0402_5%  [R0402_0OHM]  65.71 82.2 90 top
PR20  0_0402_5%  [R0402_0OHM]  59.27 81.78 0 top
PR21  0_0402_5%  [R0402_0OHM]  53.52 87.48 180 bottom
PR22  0_0402_5%  [R0402_0OHM]  50.86 87.48 0 bottom
PR23  0_0402_5%  [R0402_0OHM]  51.71 91.49 0 bottom
PR24  100K_0402_5%  [R_0402]  61 81.79 0 top
PR25  0_0402_5%  [R0402_0OHM]  61.89 83.11 90 top
PR26  0_0402_5%  [R0402_0OHM]  51.77 86.6 180 bottom
PR27  100K_0402_5%  [R_0402]  49.88 86.58 90 bottom
PR28  100K_0402_5%  [R_0402]  50.86 85.71 0 bottom
PR29  0_0402_5%  [R0402_0OHM]  51.76 83.92 90 bottom
PR30  100K_0402_5%  [R_0402]  50.87 91.51 180 bottom
PR100  0_0603_5%  [R0603_0OHM]  141.6 109.55 90 bottom
PR102  499K_0402_1%  [R_0402]  144.07 102.87 270 bottom
PR103  499K_0402_1%  [R_0402]  143.18 102.87 270 bottom
PR104  0_0402_5%  [R0402_0OHM]  139.12 101.96 270 bottom
PR105  0_0402_5%  [R0402_0OHM]  138.23 101.96 270 bottom
PR106  4.7_1206_5%  [R_1206]  138.1 108.7 270 top
PR107  100K_0402_5%  [R_0402]  145.85 101.95 90 bottom
PR108  1K_0402_5%  [R_0402]  141.41 101.95 90 bottom
PR111  0_0603_5%  [R0603_0OHM]  44.79 45.23 0 bottom
PR112  4.7_1206_5%  [R_1206]  44.51 47.41 90 top
PR113  100K_0402_5%  [R_0402]  40.32 40.7 90 top
PR114  0_0402_5%  [R0402_0OHM]  38.56 40.65 0 top
PR116  1M_0402_1%  [R_0402]  39.48 41.54 180 top
PR117  1K_0402_5%  [R_0402]  37.89 43.16 90 bottom
PR119  0_0402_5%  [R0402_0OHM]  144.96 102.87 270 bottom
PR120  0_0402_5%  [R0402_0OHM]  144.96 100.17 90 bottom
PR202  4.7_1206_5%  [R_1206]  50.68 59.61 90 bottom
PR203  0_0603_5%  [R0603_0OHM]  53.7 62.68 180 bottom
PR204  102K_0402_1%  [R_0402]  54.79 63.87 270 bottom
PR205  0_0402_5%  [R_0402]  58.34 62.97 90 bottom
PR206  100K_0402_1%  [R_0402]  56.52 62.97 90 bottom
PR207  0_0402_5%  [R_0402]  57.47 63.89 270 bottom
PR208  0_0402_5%  [R0402_0OHM]  59.44 54.96 90 top
PR209  1M_0402_5%  [R_0402]  59.22 56.73 0 top
PR210  0_0402_5%  [R0402_0OHM]  58.54 48.23 90 top
PR212  1M_0402_5%  [R_0402]  58.6 54.45 180 top
PR302  1M_0402_1%  [R_0402]  164.16 106.82 0 top
PR303  4.7_1206_5%  [R_1206]  157.15 99.81 90 top
PR304  0_0603_5%  [R0603_0OHM]  155.83 101.9 270 bottom
PR306  21.5K_0402_1%  [R_0402]  165.07 104.97 180 bottom
PR307  0_0402_5%  [R_0402]  164.16 104.09 90 top
PR308  1K_0402_5%  [R_0402]  165.08 105.9 180 bottom
PR310  0_0402_5%  [R_0402]  164.16 105.9 0 top
PR311  31.6K_0402_1%  [R_0402]  164.16 106.82 0 bottom
PR312  0_0402_5%  [R0402_0OHM]  165.08 107.7 180 top
PR402  0_0402_5%  [R0402_0OHM]  178.24 46.96 90 top
PR403  1M_0402_1%  [R_0402]  178.24 48.74 90 top
PR404  0_0402_5%  [R_0402]  173.95 47.34 0 top
PR405  4.7_0603_5%  [R_0603]  172.24 48.56 180 bottom
PR406  0_0402_5%  [R0402_0OHM]  174.63 98.24 270 top
PR407  1M_0402_1%  [R_0402]  173.74 97.33 90 top
PR408  0_0402_5%  [R_0402]  174.76 103.51 270 bottom
PR409  4.7_0603_5%  [R_0603]  168.01 98.7 0 top
PR410  0_0402_5%  [R_0402]  173.38 95.07 90 top
PR411  0_0402_5%  [R_0402]  173.87 103.51 270 bottom
PR412  0_0402_5%  [R_0402]  175.16 54.5 90 bottom
PR413  10K_0402_1%  [R_0402]  177 54.52 270 bottom
PR414  10K_0402_1%  [R_0402]  177.86 54.52 270 bottom
PR415  10K_0402_1%  [R_0402]  176.05 53.6 90 bottom
PR416  10K_0402_1%  [R_0402]  178.72 53.61 0 bottom
PR417  10K_0402_1%  [R_0402]  173.87 103.51 270 top
PR418  10K_0402_1%  [R_0402]  174.76 103.51 270 top
PR419  10K_0402_1%  [R_0402]  172.98 102.69 90 top
PR420  10K_0402_1%  [R_0402]  175.65 102.69 90 top
PR421  0_0402_5%  [R_0402]  173.38 53.64 0 bottom
PR422  0_0402_5%  [R_0402]  174.27 54.5 90 bottom
PR423  0_0402_5%  [R0402_0OHM]  171.94 102.7 180 bottom
PR424  100K_0402_1%  [R_0402]  171.94 103.57 180 bottom
PR425  0_0402_5%  [R0402_0OHM]  176.59 47.33 180 top
PR426  0_0402_5%  [R0402_0OHM]  172.5 95.07 90 top
PR427  0_0402_5%  [R_0402]  175.08 53.81 0 top
PR428  1M_0402_1%  [R_0402]  171.9 103.58 180 top
PR501  20K_0402_1%  [R_0402]  175.65 104.1 0 bottom
PR502  4.7_0603_5%  [R_0603]  169.88 108.19 0 top
PR504  0_0402_5%  [R0402_0OHM]  173.31 106.2 90 top
PR505  1M_0402_1%  [R_0402]  171.55 107.1 270 top
PR506  10K_0402_1%  [R_0402]  177.45 104.98 270 bottom
PR513  0_0402_5%  [R0402_0OHM]  218.81 10.19 90 top
PR514  1M_0402_1%  [R_0402]  219.7 11.11 270 top
PR515  21.5K_0402_1%  [R_0402]  214.36 14.56 270 top
PR516  10.2K_0402_1%  [R_0402]  215.24 12.8 180 top
PR517  100K_0402_5%  [R_0402]  175.55 107.99 270 top
PR601  45.3_0402_1%  [R_0402]  59.93 65.51 0 top
PR602  0_0402_5%  [R0402_0OHM]  61.59 68.19 180 bottom
PR603  0_0402_5%  [R0402_0OHM]  61.61 69.4 180 bottom
PR604  75_0402_1%  [R_0402]  59.93 66.38 0 top
PR605  100_0402_1%  [R_0402]  59.93 67.25 0 top
PR606  0_0402_5%  [R0402_0OHM]  88.1 88.41 90 bottom
PR608  88.7K_0402_1%  [R_0402]  65.29 67.97 0 bottom
PR610  10K_0402_1%  [R_0402]  66.57 61.42 90 top
PR611  1.87K +-1% 0402  [R_0402]  65.29 68.84 0 bottom
PR612  1.91K_0402_1%  [R_0402]  62.17 63.73 0 top
PR613  90.9K +-1% 0402  [R_0402]  65.33 65.36 270 bottom
PR614  0_0402_5%  [R0402_0OHM]  62.17 62.86 0 top
PR615  0_0402_5%  [R_0402]  87.55 81 90 top
PR616  0_0402_5%  [R0402_0OHM]  63.82 64.59 90 bottom
PR617  4.3K_0402_1%  [R_0402]  69.36 61.98 180 bottom
PR618  49.9_0402_1%  [R_0402]  62.17 65.48 0 top
PR619  2.2_0603_5%  [R_0603]  85.53 86.85 270 bottom
PR620  0_0402_5%  [R0402_0OHM]  65.25 63.19 0 top
PR621  316_0402_1%  [R_0402]  68.25 59.48 90 top
PR622  1.91K_0402_1%  [R_0402]  67.62 61.39 90 top
PR623  2K_0402_1%  [R_0402]  67.37 59.48 90 top
PR624  3.65K_0603_1%  [R_0603]  62.67 72.25 270 bottom
PR625  0_0402_5%  [R0402_0OHM]  62.17 66.36 0 top
PR626  10_0402_1%  [R_0402]  62.16 67.23 0 top
PR627  4.7_1206_5%  [R_1206]  93.77 85.97 270 top
PR628  4.99K_0402_1%  [R_0402]  85.83 74.48 270 top
PR629  88.7K_0402_1%  [R_0402]  70.26 66.38 0 bottom
PR630  2.49K_0402_1%  [R_0402]  69.13 71.58 90 top
PR631  27.4K_0402_1%  [R_0402]  66.22 63.53 180 bottom
PR632  1K_0402_1%  [R_0402]  70.61 61.4 0 top
PR633  11K_0402_1%  [R_0402]  69.77 62.3 270 top
PR634  0_0402_5%  [R_0402]  88.43 81 90 top
PR635  10K_0402_1%  [R_0402]  74.03 64.15 180 top
PR636  665 +-1% 0402  [R_0402]  65.62 71.56 90 top
PR638  374_0402_1%  [R_0402]  74.62 62.21 90 bottom
PR639  3.09K_0402_1%  [R_0402]  74.03 65.03 180 top
PR640  374_0402_1%  [R_0402]  72.16 70.23 0 top
PR641  1K_0402_1%  [R_0402]  65.13 73.33 0 top
PR642  2.61K_0402_1%  [R_0402]  64 70.84 90 bottom
PR643  11K_0402_1%  [R_0402]  65.93 72.49 270 bottom
PR644  1K_0402_1%  [R_0402]  73.96 71.1 270 top
PR645  316_0402_1%  [R_0402]  74.03 65.95 180 bottom
PR646  316_0402_1%  [R_0402]  68.25 71.58 90 top
PR647  27.4K_0402_1%  [R_0402]  74.91 63.22 90 top
PR648  1.91K_0402_1%  [R_0402]  74.03 66.82 180 bottom
PR649  1.62K_0402_1%  [R_0402]  66.82 71.57 90 bottom
PR650  2K_0402_1%  [R_0402]  72.73 65.04 0 bottom
PR651  113K_0402_1%  [R_0402]  70.46 70.08 270 bottom
PR652  2K_0402_1%  [R_0402]  67.69 71.57 90 bottom
PR653  20M_0402_5%  [R_0402]  71.33 69.17 90 bottom
PR656  11K_0402_1%  [R_0402]  73.97 69.78 90 bottom
PR657  4.42K_0402_1%  [R_0402]  74.79 54.16 180 top
PR658  20M_0402_5%  [R_0402]  76.24 66.04 270 bottom
PR659  0_0402_5%  [R0402_0OHM]  83.8 56.45 90 bottom
PR660  3.9_0603_1%  [R_0603]  81 55.91 90 bottom
PR661  3.65K_0603_1%  [R_0603]  74.79 51.82 90 top
PR662  0_0402_5%  [R0402_0OHM]  65.54 49.22 180 top
PR663  4.7_1206_5%  [R_1206]  79.98 63.8 180 top
PR664  0_0402_5%  [R0402_0OHM]  62.2 48.61 0 bottom
PR665  3.9_0603_1%  [R_0603]  61.6 51.55 0 bottom
PR666  10_0402_1%  [R_0402]  78.05 62.3 180 bottom
PR667  3.65K_0603_1%  [R_0603]  77.17 65.32 0 bottom
PR668  100K_0402_1%  [R_0402]  78.34 64.22 180 bottom
PR669  4.7_1206_5%  [R_1206]  72.67 51.24 180 top
PR670  100K_0402_1%  [R_0402]  88.18 79.19 180 bottom
PR671  0_0402_5%  [R_0402]  71.42 76.15 0 bottom
PR672  3.9_0603_1%  [R_0603]  71.61 80.2 270 bottom
PR673  10_0402_1%  [R_0402]  87.27 78.28 0 bottom
PR674  3.65K_0603_1%  [R_0603]  87.46 82.74 270 bottom
PR675  100K_0402_1%  [R_0402]  87.46 80.31 0 bottom
PR676  4.7_1206_5%  [R_1206]  83.39 81.68 180 top
PR677  100K_0402_1%  [R_0402]  78.06 63.23 180 bottom
PR678  100_0402_1%  [R_0402]  62.16 64.6 0 top
PR679  0_0402_5%  [R0402_0OHM]  85.73 84.5 180 bottom
PR680  1_0603_5%  [R_0603]  66.08 51 180 top
PR681  10K_0402_1%  [R_0402]  65.32 47.52 180 top
PR682  -  [SOLDER_PREFORMS_0603]  113.7 66.42 180 top
PR683  -  [SOLDER_PREFORMS_0603]  110.85 66.41 0 top
PR684  -  [SOLDER_PREFORMS_0603]  113.9 60.78 180 top
PR686  10K_0402_1%  [R_0402]  74.87 62.37 0 top
PR687  0_0402_5%  [R0402_0OHM]  85.55 57.35 180 bottom
PR688  1_0603_5%  [R_0603]  86.68 60.33 90 bottom
PR689  10K_0402_1%  [R_0402]  72.7 76.41 270 top
PR691  1_0603_5%  [R_0603]  72.99 77.43 180 top
PR692  0_0402_5%  [R_0402]  71.39 75.21 0 bottom
PR901  0.01_1206_1%  [R_1206_4P-D]  23.69 44.81 270 bottom
PR909  2_0603_1%  [R_0603]  27.74 40.41 0 bottom
PR910  2_0603_1%  [R_0603]  27.74 39.2 0 bottom
PR914  3.3_0603_1%  [R_0603]  31.37 39.81 270 bottom
PR915  4.7_0603_5%  [R_0603]  34.08 40.41 270 bottom
PR916  1_0805_5%~D  [R_0805]  28.71 40.92 180 top
PR917  0.005_1206_1%  [R_1206_4P-D]  35.74 25.56 0 top
PR918  100K_0402_1%  [R_0402]  26.59 44.98 0 top
PR919  0_0402_5%  [R_0402]  26.1 43.71 0 bottom
PR920  0_0402_5%  [R0402_0OHM]  26.1 44.58 0 bottom
PR921  4.7_0603_5%  [R_0603]  35.36 41.75 0 bottom
PR922  0_0402_5%  [R0402_0OHM]  26.11 45.45 0 bottom
PR923  4.7_1206_5%  [R_1206]  38.64 35.59 180 top
PR924  4.7_1206_5%  [R_1206]  38.28 29.33 180 top
PR925  154K_0402_1%  [R_0402]  23.55 47.42 180 bottom
PR926  0_0402_5%  [R0402_0OHM]  26.12 46.39 0 bottom
PR927  1M_0402_1%  [R_0402]  22.38 48.09 270 top
PR928  0_0402_5%  [R0402_0OHM]  26.12 47.41 0 bottom
PR929  0_0402_5%  [R0402_0OHM]  35.4 43.98 0 bottom
PR930  100K_0402_1%  [R_0402]  27.61 46.03 180 top
PR931  100K_0402_1%  [R_0402]  28.46 46.95 270 top
PR932  105K_0402_1%  [R_0402]  29.98 46.7 270 top
PR933  100K_0402_1%  [R_0402]  30.04 48.99 270 top
PR934  499_0402_1%  [R_0402]  30.92 48.07 90 top
PR935  0_0402_5%  [R0402_0OHM]  31.85 49.86 0 top
PR936  0_0402_5%  [R0402_0OHM]  31.71 48.3 0 bottom
PR937  1_0603_1%  [R_0603]  36.01 45.09 0 bottom
PR938  1_0603_1%  [R_0603]  36.01 46.31 0 bottom
PR939  0_0402_5%  [R0402_0OHM]  21.75 50.08 0 top
PR940  100_0402_5%  [R_0402]  35.89 45.56 180 top
PR941  0_0402_5%  [R0402_0OHM]  21.75 50.98 0 top
PR942  0_0402_5%  [R0402_0OHM]  25.96 48.66 90 top
PR943  0_0603_5%  [R_0603]  25.14 42.58 0 top
PR944  442K_0402_1%  [R_0402]  26.13 43.61 0 top
PR945  100K_0402_5%  [R_0402]  28.33 44.59 0 top
PR946  0_0402_5%  [R0402_0OHM]  29.11 47.79 180 top
PR947  0_0402_5%  [R0402_0OHM]  31.85 48.99 0 top
PR948  12.7K_0402_1%  [R_0402]  30.89 48.29 180 bottom
PR950  0_0402_5%  [R_0402]  28.13 52.02 0 top
PR951  0_0402_5%  [R0402_0OHM]  31.12 51.81 180 top
PR953  100K_0402_1%  [R_0402]  27.36 47.79 180 top
PR960  0_0402_5%  [R0402_0OHM]  25.47 42.83 0 bottom
PR961  100K_0402_1%  [R_0402]  25.96 51.55 0 top
PR1201  240K_0402_1%  [R_0402]  55.34 78.76 0 top
PR1202  300K_0402_5%  [R_0402]  50.8 72.39 0 top
PR1203  1.8M_0402_1%  [R_0402]  57.08 78.76 0 top
PR1205  499K_0402_1%  [R_0402]  40.82 64.05 90 top
PR1206  1K_0402_1%  [R_0402]  57.98 80.54 270 top
PR1207  499K_0402_1%  [R_0402]  35.97 74.14 270 top
PR1208  102K_0402_1%  [R_0402]  60.61 78 180 top
PR1209  100K_0402_5%  [R_0402]  52.56 72.39 0 top
PR1210  1M_0402_5%  [R_0402]  43.23 73.28 180 top
PR1211  0_0402_5%  [R0402_0OHM]  40.46 75.41 90 top
PR1212  49.9K_0402_1%  [R_0402]  39.49 67.31 90 top
PR1213  49.9K_0402_1%  [R_0402]  35.96 72.37 0 top
PR1214  100K_0402_5%  [R_0402]  39.63 73.26 270 top
PR1215  0_0402_5%  [R0402_0OHM]  37.98 77.29 0 top
PR1216  0_0402_5%  [R0402_0OHM]  37.84 72.36 90 top
PR1217  84.5K_0402_1%  [R_0402]  59.73 78.85 90 top
PR1218  0_0402_5%  [R0402_0OHM]  35.09 72.37 180 top
PR1219  23.2K_0402_1%  [R_0402]  57.1 79.62 90 top
PR1220  0_0402_5%  [R0402_0OHM]  37.71 68.19 0 top
PR1221  0_0402_5%  [R0402_0OHM]  38.74 79.29 270 top
PR1222  100K_0402_5%  [R_0402]  37.71 67.32 0 top
PR1223  0_0402_5%  [R0402_0OHM]  35.97 68.19 0 top
PR1224  100K_0402_5%  [R_0402]  37.86 78.38 90 top
PR1225  0_0402_5%  [R0402_0OHM]  36.91 78.38 90 top
PR1226  100K_0402_5%  [R_0402]  35.1 73.22 90 top
PR1227  100K_0402_5%  [R_0402]  19.05 79.94 0 bottom
PR1228  499K_0402_1%  [R_0402]  39.97 64.91 180 top
PR1229  49.9K_0402_1%  [R_0402]  39.06 65.78 0 top
PR1230  100K_0402_5%  [R_0402]  42.16 55.46 0 top
PR1231  100K_0402_5%  [R_0402]  41.76 56.33 0 top
PR1232  100K_0402_5%  [R_0402]  45.38 53.83 0 top
PR1233  100K_0402_5%  [R_0402]  47.16 57.36 0 top
PR1234  100K_0402_5%  [R_0402]  47.15 54.7 0 top
PR1235  100K_0402_5%  [R_0402]  47.16 56.49 0 top
PR1236  100K_0402_5%  [R_0402]  61.68 73.52 90 top
PR1237  100K_0402_1%  [R_0402]  56.52 70.32 90 top
PR1238  0_0402_5%  [R0402_0OHM]  53.51 75.24 90 top
PR1239  150K_0402_1%  [R_0402]  52.64 76.15 270 top
